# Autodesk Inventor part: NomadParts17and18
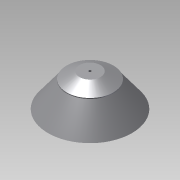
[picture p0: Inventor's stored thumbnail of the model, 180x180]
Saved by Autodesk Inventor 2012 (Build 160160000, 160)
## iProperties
Created: 2012-10
Part Number: NomadParts17and18
Material: Default
Document SubType Name: Modeling
Designer: TechShop Member
Density: 1 g/cm^3
Author: TechShop Member
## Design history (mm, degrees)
sketch "Sketch1"
  geometry: L1 (0, 0)-(0, 53.34); L2 (0, 53.34)-(0, 55.049); L3 (0, 55.049)-(0, 69.596); L4 (0, 69.596)-(22.225, 69.596); L5 (22.225, 69.596)-(49.53, 55.049); L6 (49.53, 55.049)-(49.53, 53.34); L7 (0, 0)-(88.9, 0); L8 (49.53, 53.34)-(88.9, 0)
  constraints: 16 end point, 2 collinear, 2 perpendicular, 1 vertical
  dimensions: "d0" = 53.34 distance of L1.start L1.end; "d1" = 1.70942 distance of L1.end L2.end; "d2" = 14.54658 distance of L2.end L3.end; "d4" = 49.53 distance of L2.end L5.end; "d6" = 22.225 distance of L3.end L4.end; "d7" = 88.9 distance of L1.start L7.end
revolve "Revolution1" sketch "Sketch1" stored, may be unused: angle "d8" = 90 deg
sketch "Sketch2"
  geometry: C1 r 22.225 at (0, 0) reference; 1 further point
  constraints: 1 coincident
hole "Hole1" sketch "Sketch2" at (0, 0) diameter "d9" = 5.207; stored, may be unused: countersink angle "d13" = 82 deg, drill point angle "d15" = 118 deg; dims "d10" = 19.05, "d11" = 9.525, "d12" = 6.35, "d14" = 25.4
body "Solid1"
